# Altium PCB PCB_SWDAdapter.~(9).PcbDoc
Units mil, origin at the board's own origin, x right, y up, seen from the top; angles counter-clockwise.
Board outline 1010 x 725 mil, 2 copper layers (Top Layer, Bottom Layer); 3 components, 6 nets, 18 pads, 1 vias.
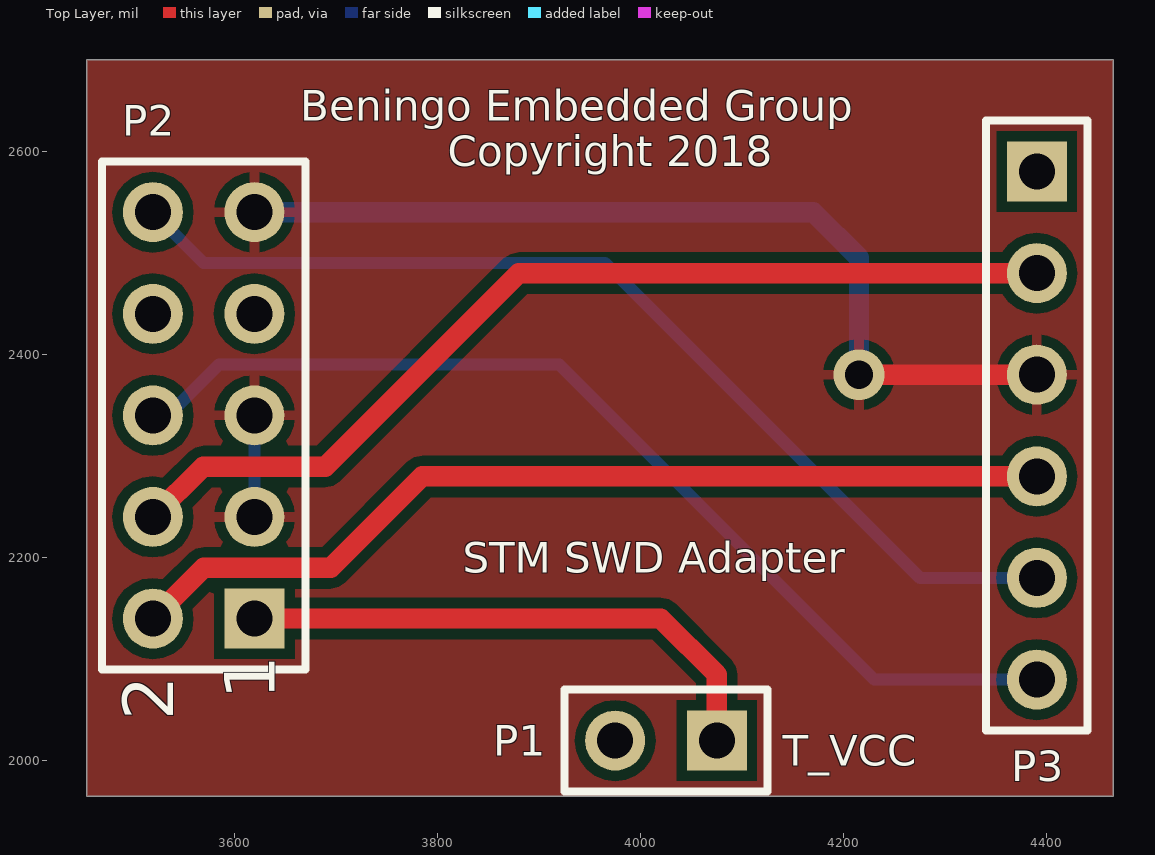
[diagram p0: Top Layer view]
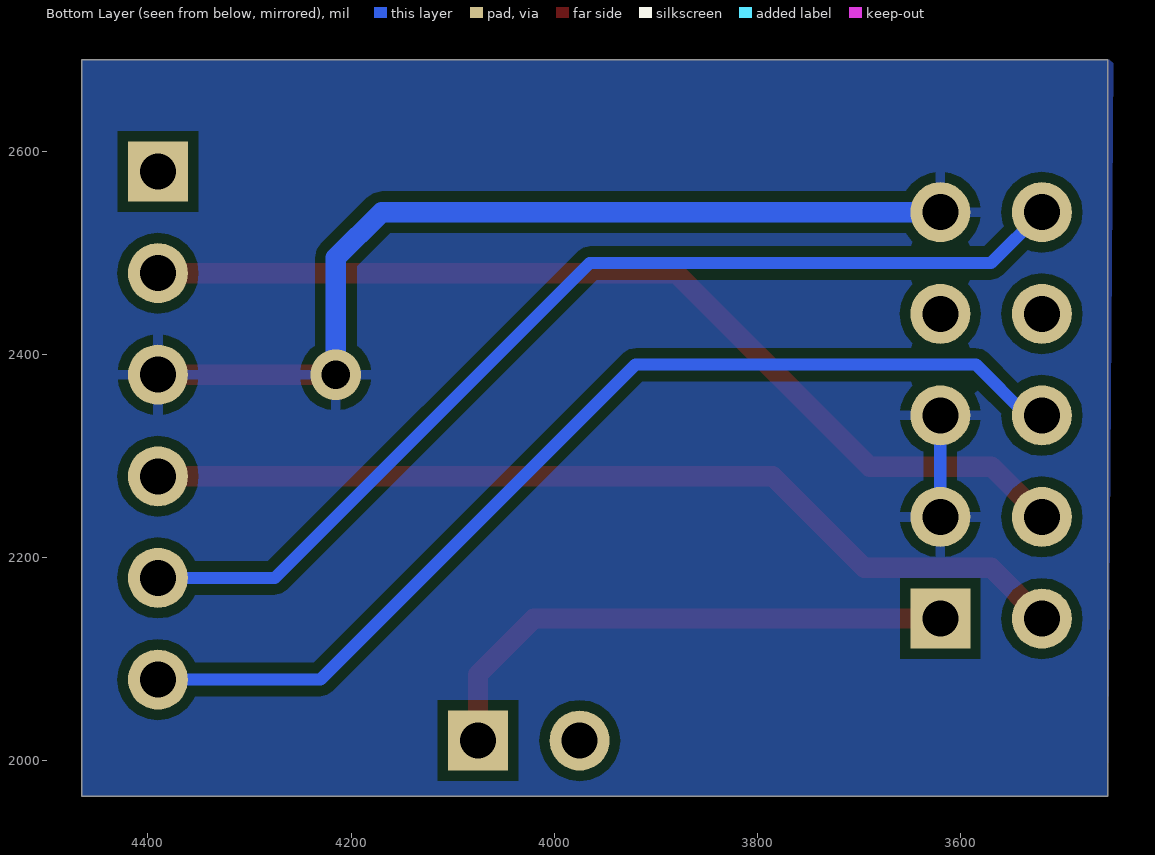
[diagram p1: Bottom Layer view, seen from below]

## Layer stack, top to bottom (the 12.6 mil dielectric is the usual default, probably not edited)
Top Solder: solder mask 0.4, Solder Resist, Dk 3.5
Top Layer: signal copper 1.4
Dielectric 1: dielectric 12.6, FR-4, Dk 4.8
Bottom Layer: signal copper 1.4
Bottom Solder: solder mask 0.4, Solder Resist, Dk 3.5

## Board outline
3455,1965 4465,1965 4465,2690 3455,2690

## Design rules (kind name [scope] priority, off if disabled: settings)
Clearance [All] p1: gap=10
PolygonConnect [All] p1: connectstyle=Relief reliefconductorwidth=10 reliefentries=4 polygonreliefangle="90 Angle" airgapwidth=10
RoomDefinition SCH_Adapter [InComponentClass('SCH_Adapter')] p1: confinementstyle=ConfineIn formatcopy=TRUE lockcomponents=FALSE outline 3455,1945 4475,1945 4475,2710 3455,2710
RoutingVias [All] p1: holewidth=28 width=50 viastyle="Through Hole" minholewidth=28 minwidth=50 maxholewidth=28 maxwidth=50
SolderMaskExpansion [All] p1: expansion=4
Width [All] p1: maxlimit=20 minlimit=10 preferedwidth=10 minimp=50.000000 maximp=50.000000 favimp=50.000000
30 further rules are at their usual default settings.

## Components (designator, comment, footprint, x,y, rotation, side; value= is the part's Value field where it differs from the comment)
P1 "Target VDD" HDR1X2 4075,2020 r180 top
P2 "ARM 10-Pin SWD" HDR2X5 3620,2140 r90 top
P3 "SWD Target" HDR1X6 4390,2580 r270 top

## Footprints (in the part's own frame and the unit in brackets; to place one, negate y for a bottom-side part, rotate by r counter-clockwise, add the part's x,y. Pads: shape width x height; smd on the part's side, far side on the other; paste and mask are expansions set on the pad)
HDR1X2 [mm] "Connector; Header; 2 Position"
  rect 1.5x1.5 hole 0.9: 1(0,0)
  round 1.5 hole 0.9: 2(2.54,0)
  silkscreen extent -1.27,-1.27 3.81,1.27
HDR1X6 [mm] "Connector; Header; 6 Position"
  rect 1.5x1.5 hole 0.9: 1(0,0)
  round 1.5 hole 0.9: 2(2.54,0) 3(5.08,0) 4(7.62,0) 5(10.16,0) 6(12.7,0)
  silkscreen extent -1.27,-1.27 13.97,1.27
HDR2X5 [mm] "Connector; Header; 5x2 Position"
  rect 1.5x1.5 hole 0.9: 1(0,0)
  round 1.5 hole 0.9: 2(0,2.54) 3(2.54,0) 4(2.54,2.54) 5(5.08,0) 6(5.08,2.54) 7(7.62,0) 8(7.62,2.54) 9(10.16,0) 10(10.16,2.54)
  silkscreen extent -1.27,-1.27 11.43,3.81

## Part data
P1: library part "Header 2", "Header, 2-Pin"
P2: library part "Header 5X2", "Header, 5-Pin, Dual row"
P3: library part "Header 6", "Header, 6-Pin"

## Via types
v1: diameter 50, hole 28, Top Layer to Bottom Layer, 1 vias

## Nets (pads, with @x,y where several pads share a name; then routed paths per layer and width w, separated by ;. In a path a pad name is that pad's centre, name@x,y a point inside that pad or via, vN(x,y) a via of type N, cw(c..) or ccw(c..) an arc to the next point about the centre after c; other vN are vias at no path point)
GND: P2.3 P2.5 P2.9 P3.3 | length 1003.6
  Top Layer w20: v1(4215,2380) P3.3
  Bottom Layer w12: P2.3 P2.5
  Bottom Layer w20: P2.9 4170,2540 4215,2495 v1(4215,2380)
NRST: P2.10 P3.5 | length 1019.1
  Bottom Layer w12: P2.10 3570,2490 3965,2490 4275,2180 P3.5
SWCLK: P2.4 P3.2 | length 969.4
  Top Layer w20: P2.4 3569.53,2289.53 3689.53,2289.53 3880,2480 P3.2
SWDIO: P2.2 P3.4 | length 928
  Top Layer w20: P2.2 3570,2190 3695,2190 3785,2280 P3.4
SWO: P2.6 P3.6 | length 1019.1
  Bottom Layer w12: P2.6 3535,2340 3585,2390 3920,2390 4230,2080 P3.6
TARGETVCC: P1.1 P2.1 | length 542.8
  Top Layer w20: P2.1 4020,2140 4075,2085 P1.1
pads on no net: P1.2 P2.7 P2.8 P3.1

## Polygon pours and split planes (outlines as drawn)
GND on Top Layer "TopPour" (solid, remove dead copper, pour order 0): 3455,2690 4465,2690 4465,1965 3455,1965
GND on Bottom Layer "BottomPout" (solid, remove dead copper, pour order 2): 3450,2690 4465,2690 4465,1965 3455,1965

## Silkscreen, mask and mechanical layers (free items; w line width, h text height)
Top Overlay:
  text "Beningo Embedded Group" at 3665,2630 h30
  text "Copyright 2018" at 3810,2585 h30
  text "STM SWD Adapter" at 3825,2185 h30
  text "T_VCC" at 4140,1995 h30
Mechanical 1:
  the board outline again, w10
